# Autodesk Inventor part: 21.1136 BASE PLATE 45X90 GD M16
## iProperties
Created: 2007-03
Part Number: 21.1136 BASE PLATE 45X90 GD M16
Document SubType Name: Modeling
Designer: Andy Moles
Material: Aluminum-6061
Mass: 147.086 g
Surface Area: 129.98 cm^2
Volume: 54.2754 cm^3
Density: 2.71 g/cm^3
Author: Andy Moles
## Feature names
1. Extrusion1
2. Hole1
3. Hole2
4. Fillet1
